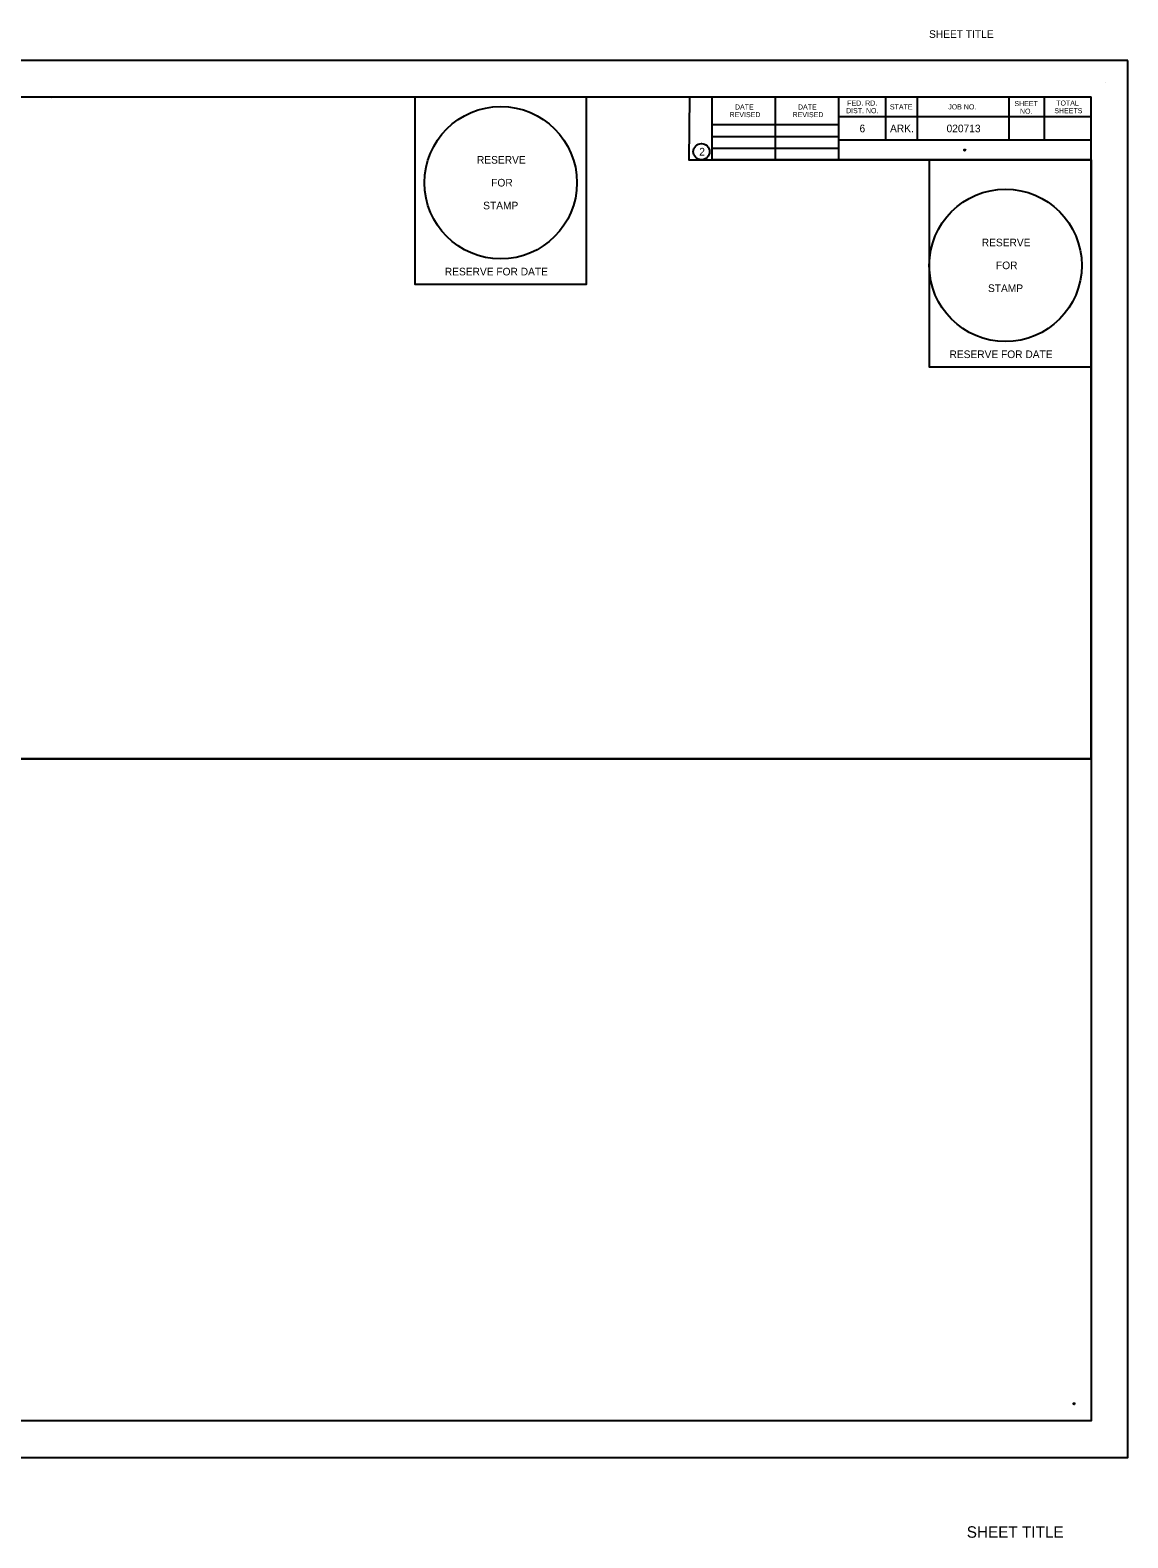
# Model space of a CAD drawing. Extents: x 0 to 17, y -0.6 to 11.2.
# Drawn here: x 8.36 to 17, y -0.63 to 11.24 of the extents above; entities that cross this region are included whole.
import ezdxf

# ---------------------------------------------------------------- set-up
doc = ezdxf.new("R2010")
doc.units = 0
for name, color, linetype in [('G-ANNO-TEXT', 7, 'Continuous'), ('G-Border-Paper', 7, 'Continuous'), ('G-Border-Sheet', 7, 'Continuous'), ('G-No Plot-Anchor', 7, 'Continuous'), ('G-No Plot-Border-1', 7, 'Continuous'), ('G-No Plot-Border-2', 7, 'Continuous'), ('G-No Plot-Stamp-1', 7, 'Continuous'), ('G-No Plot-Stamp-2', 7, 'Continuous'), ('G-Table-Major', 7, 'Continuous'), ('G-Table-Minor', 7, 'Continuous')]:
    doc.layers.add(name, color=color, linetype=linetype)

msp = doc.modelspace()

# ---------------------------------------------------------------- linework, layer by layer
at = {"layer": 'G-ANNO-TEXT'}
msp.add_line((16.821, 10.827), (16.821, 10.827), dxfattribs=at)
at = {"layer": 'G-Border-Paper'}
msp.add_lwpolyline([(17, 11), (0, 11), (0, 0), (17, 0)], close=True, dxfattribs=at)
at = {"layer": 'G-Border-Sheet'}
for p in [(0.758, 10.712), (16.712, 5.5)]:
    msp.add_line(p, (16.712, 10.712), dxfattribs=at)
msp.add_lwpolyline([(0.758, 5.5), (16.712, 5.5), (16.712, 0.288), (0.758, 0.288)], close=True, dxfattribs=at)
at = {"layer": 'G-No Plot-Anchor'}
for centre in [(15.716, 10.294), (16.577, 0.423)]:
    msp.add_circle(centre, 0.005, dxfattribs=at)
at = {"layer": 'G-No Plot-Border-1'}
msp.add_lwpolyline([(0.758, 5.5), (0.758, 10.712), (12.738, 10.712), (12.738, 10.712), (12.738, 10.712), (13.548, 10.712), (13.545, 10.216), (14.721, 10.216), (14.721, 10.216), (15.437, 10.216), (15.437, 8.586), (16.712, 8.586), (16.712, 5.5)], close=True, dxfattribs=at)
at = {"layer": 'G-No Plot-Border-2'}
msp.add_lwpolyline([(0.758, 5.5), (0.758, 10.712), (11.388, 10.712), (11.388, 9.237), (12.738, 9.237), (12.738, 10.216), (12.738, 10.712), (13.548, 10.712), (13.545, 10.216), (14.721, 10.216), (14.721, 10.216), (16.712, 10.216), (16.712, 5.5)], close=True, dxfattribs=at)
at = {"layer": 'G-No Plot-Stamp-1'}
msp.add_circle((16.037, 9.386), 0.6, dxfattribs=at)
at = {"layer": 'G-No Plot-Stamp-2'}
msp.add_circle((12.063, 10.037), 0.6, dxfattribs=at)
at = {"layer": 'G-Table-Major'}
for p, q in [((13.728, 10.217), (13.728, 10.712)), ((14.721, 10.712), (14.721, 10.216)), ((13.728, 10.495), (14.721, 10.495)), ((16.712, 10.216), (13.728, 10.216))]:
    msp.add_line(p, q, dxfattribs=at)
msp.add_circle((13.643, 10.281), 0.0638, dxfattribs=at)
at = {"layer": 'G-Table-Minor'}
for p, q in [((8.529, 10.699), (8.529, 10.699)), ((8.529, 10.699), (8.529, 10.699)), ((14.226, 10.216), (14.226, 10.712)), ((15.093, 10.712), (15.093, 10.372)), ((15.341, 10.712), (15.341, 10.372)), ((16.062, 10.712), (16.062, 10.372)), ((16.34, 10.712), (16.34, 10.372)), ((16.712, 10.566), (16.712, 10.566)), ((16.712, 10.556), (14.721, 10.556)), ((13.728, 10.401), (14.721, 10.401)), ((16.712, 10.372), (14.721, 10.372)), ((13.728, 10.31), (14.721, 10.31))]:
    msp.add_line(p, q, dxfattribs=at)

# ---------------------------------------------------------------- texts
at = {"layer": 'G-ANNO-TEXT'}
for s, height, p in [('SHEET TITLE', 0.06, (15.435, 11.177)), ('TOTAL', 0.04, (16.436, 10.644)), ('REVISED', 0.04, (13.865, 10.553)), ('DATE', 0.04, (13.907, 10.613)), ('REVISED', 0.04, (14.361, 10.553)), ('DATE', 0.04, (14.403, 10.613)), ('DIST. NO.', 0.04, (14.782, 10.584)), ('FED. RD.', 0.04, (14.791, 10.644)), ('STATE', 0.04, (15.127, 10.614)), ('JOB NO.', 0.04, (15.586, 10.614)), ('SHEET', 0.04, (16.107, 10.64)), ('NO.', 0.04, (16.151, 10.58)), ('SHEETS', 0.04, (16.421, 10.584)), ('6', 0.06, (14.888, 10.434)), ('ARK.', 0.06, (15.128, 10.434)), ('020713', 0.06, (15.573, 10.434)), ('2', 0.06, (13.626, 10.251)), ('SHEET TITLE', 0.09, (15.732, -0.632))]:
    msp.add_text(s, height=height, dxfattribs=at).set_placement(p)
at = {"layer": 'G-No Plot-Stamp-1'}
for s, p in [('RESERVE', (15.85, 9.536)), ('FOR ', (15.962, 9.356)), ('STAMP', (15.899, 9.176)), ('RESERVE FOR DATE', (15.596, 8.656))]:
    msp.add_text(s, height=0.06, dxfattribs=at).set_placement(p)
at = {"layer": 'G-No Plot-Stamp-2'}
for s, p in [('RESERVE', (11.876, 10.187)), ('FOR ', (11.988, 10.007)), ('STAMP', (11.925, 9.827)), ('RESERVE FOR DATE', (11.623, 9.307))]:
    msp.add_text(s, height=0.06, dxfattribs=at).set_placement(p)

doc.saveas('drawing.dxf')
